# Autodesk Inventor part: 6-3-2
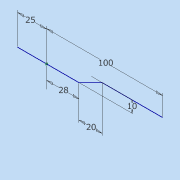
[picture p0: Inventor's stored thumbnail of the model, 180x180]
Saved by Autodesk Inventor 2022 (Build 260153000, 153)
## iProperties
Created: 2021-07
Part Number: 6-3-2
Material: 一般
Document SubType Name: Modeling
Designer: DesignLab
Density: 1 g/cm^3
Appearance: 既定
Author: DesignLab
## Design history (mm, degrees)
sketch "スケッチ1"
  geometry: L1 (25, 0)-(-28, 0); L2 (-28, 0)-(-48, 10); L3 (-48, 10)-(-100, 10); 1 further point
  constraints: 6 end point, 1 horizontal, 1 parallel, 1 point on line
  dimensions: "d0" = 25 dimension on point (0, 0) L1.start L1.end L1 L2.end L2 L3.end L3; "d0" = 25 distance of point (0, 0) L1.start; "d1" = 100 horizontal distance of L3.end point (0, 0); "d2" = 10 distance between parallel lines of L1 L3; "d3" = 28 distance of L1.end point (0, 0); "d4" = 20 horizontal distance of L1.end L2.end
